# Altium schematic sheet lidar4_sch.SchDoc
size A4; PageSetup: Record=PageOptions¦CenterHorizontal=True¦CenterVertical=True¦PrintScale=1.00¦XCorrection=1.00¦YCorrection=1.00¦PrintKind=0¦BorderSize=5000000¦LeftOffset=0¦BottomOffset=0¦Orientation=2¦PaperLength=1000¦PaperWidth=1000¦Scale=100¦PaperSource=7¦PrintQuality=-3¦MediaType=1¦DitherType=10¦PrintScaleMode=1¦PaperKind=A4¦PaperIndex=9
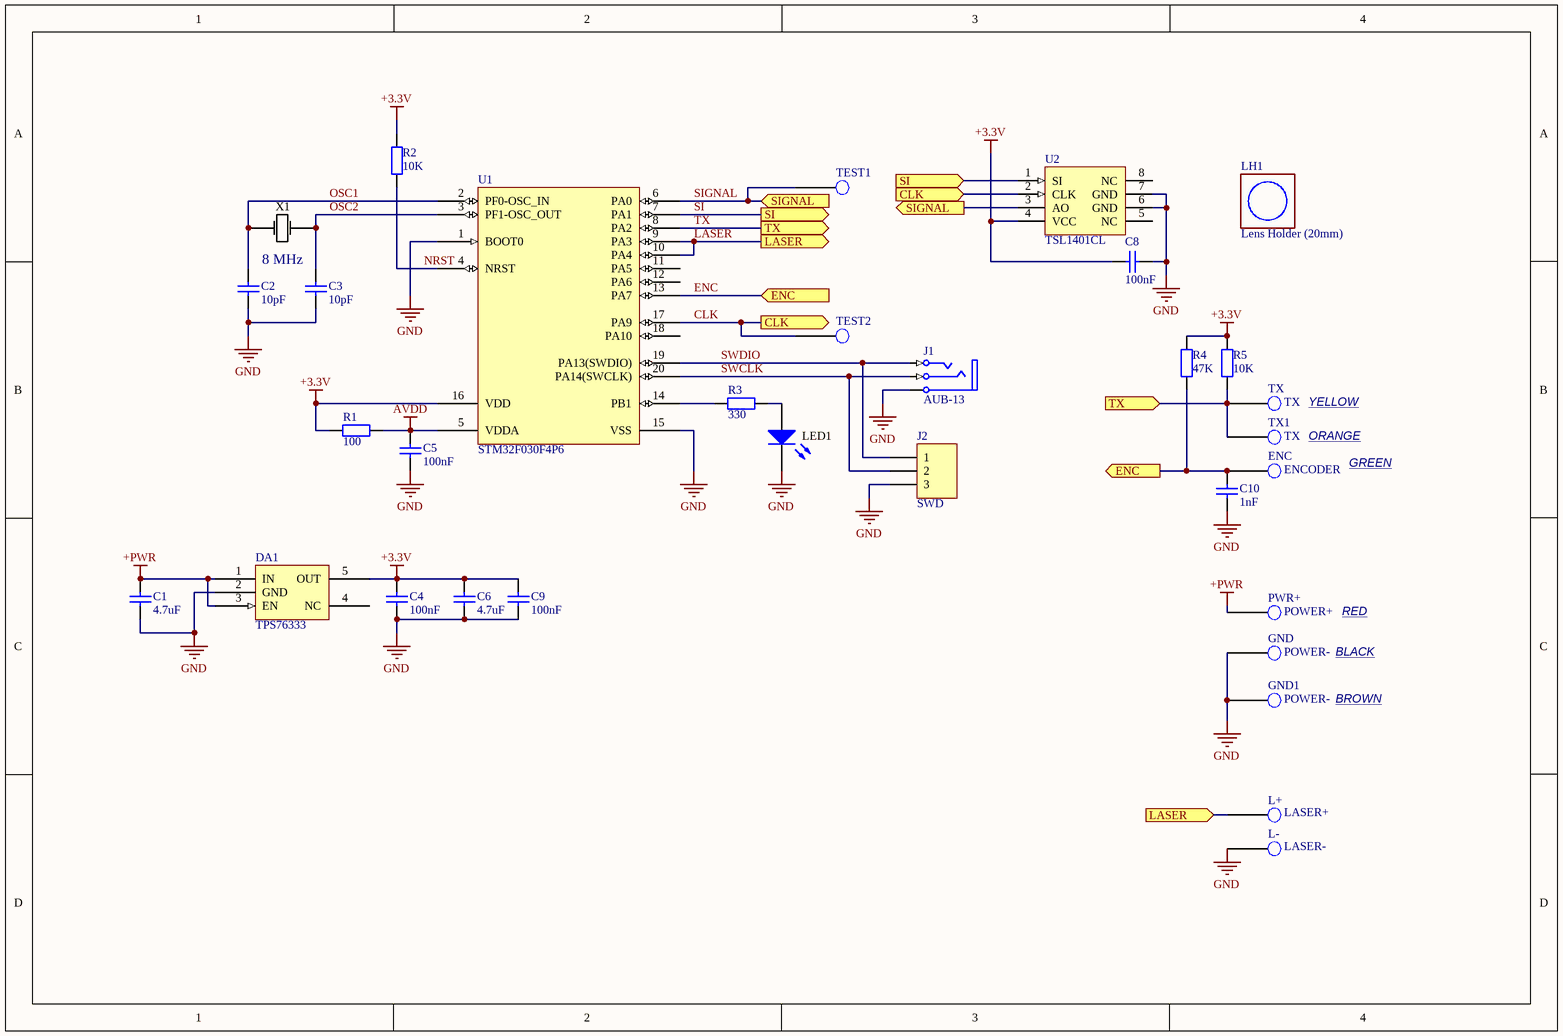
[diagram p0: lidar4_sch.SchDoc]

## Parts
C1  4.7uF  [CAPC2012X135N]
C2  10pF  [CAPC1608X90N]
C3  10pF  [CAPC1608X90N]
C4  100nF  [CAPC1608X90N]
C5  100nF  [CAPC1608X90N]
C6  4.7uF  [CAPC2012X135N]
C8  100nF  [CAPC1608X90N]
C9  100nF  [CAPC1608X90N]
C10  1nF  [CAPC1608X90N]
DA1  TPS76333  [SOT23-5]
ENC  ENCODER  [Ext_hole]
GND  POWER-  [Ext_hole]
GND1  POWER-  [Ext_hole]
J1  AUB-13  [AUB-13]
J2  SWD  [HDR1X3]
L+  LASER+  [Ext_hole]
L-  LASER-  [Ext_hole]
LED1  LED  [LED_0603]  (value not drawn)
LH1  Lens Holder (20mm)  [LENS_HOLDER_20MM_ADJ]
PWR+  POWER+  [Ext_hole]
R1  100  [RESC1608X55N]
R2  10K  [RESC1608X55N]
R3  330  [RESC1608X55N]
R4  47K  [RESC1608X55N]
R5  10K  [RESC1608X55N]
TEST1  Pad  [Ext_pad]  (value not drawn)
TEST2  Pad  [Ext_pad]  (value not drawn)
TX  TX  [Ext_hole]
TX1  TX  [Ext_hole]
U1  STM32F030F4P6  [TSSOP65P640X120-20N]
U2  TSL1401CL  [TSL1401CL_2]
X1  value 8 MHz  [SX-6 QUARTZ]  (hidden comment: Quartz)

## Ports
CLK (in), CLK (out), ENC (in), ENC (out), LASER (in), LASER (out), SI (in), SI (out), SIGNAL (in), SIGNAL (out), TX (in), TX (out)

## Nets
+3.3V: C4.2 C6.2 C8.2 C9.2 DA1.5(OUT) R1.1 R2.1 R4.1 R5.1 U1.16(VDD) U2.4(VCC)
+PWR: C1.2 DA1.1(IN) DA1.3(EN) PWR+.1(Pad)
AVDD: C5.2 R1.2 U1.5(VDDA)
GND: C1.1 C2.1 C3.1 C4.1 C5.1 C6.1 C8.1 C9.1 C10.1 DA1.2(GND) GND.1(Pad) GND1.1(Pad) J1.5(S) J2.3 L-.1(Pad) LED1.2(K) U1.1(BOOT0) U1.15(VSS) U2.6(GND) U2.7(GND)
CLK: TEST2.1(Pad) U1.17(PA9) U2.2(CLK) ; port CLK
ENC: C10.2 ENC.1(Pad) R4.2 U1.13(PA7) ; port ENC
LASER: L+.1(Pad) U1.9(PA3) U1.10(PA4) ; port LASER
NRST: R2.2 U1.4(NRST)
OSC1: C2.2 U1.2(PF0-OSC_IN) X1.1
OSC2: C3.2 U1.3(PF1-OSC_OUT) X1.3
SI: U1.7(PA1) U2.1(SI) ; port SI
SIGNAL: TEST1.1(Pad) U1.6(PA0) U2.3(AO) ; port SIGNAL
SWCLK: J1.3(R) J2.2 U1.20(PA14(SWCLK))
SWDIO: J1.1(T) J2.1 U1.19(PA13(SWDIO))
TX: R5.2 TX.1(Pad) TX1.1(Pad) U1.8(PA2) ; port TX
NetLED1_1: LED1.1(A) R3.1
NetR3_2: R3.2 U1.14(PB1)

Not connected (* = marked no-connect by the designer): DA1 4(NC); U1 11(PA5) 12(PA6) 18(PA10); U2 5(NC) 8(NC)

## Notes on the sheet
- YELLOW
- ORANGE
- GREEN
- BLACK
- RED
- BROWN

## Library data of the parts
C1-C6 C8-C10 = CC0805: Chip capacitor; Voltage: 25V
DA1 = TPS76333: LDO
ENC GND GND1 L+ L- PWR+ TEST1 TEST2 TX TX1 = Ext Pad: Pad for wire
J1 = Phonejack3: Jack Socket, 1/4" [6.5mm], Thru-Hole, Vertical, 3-Conductor Open Circuit (Non-Normalling); PackageDocument: 2003; PCB_Layout: Complies with manufacturer's recommendation.; DrillAndSlotSize: Corresponds to nominal value.
J2 = Header 3: Header, 3-Pin
LED1 = LED_0603
LH1 = M12 Lens Holder
R1-R5 = RC0805: Chip resistor; Tolerance: 5%
U1 = STM32F030F4P6: Value-line ARM-based 32-bit MCU with 16 to 64-KB Flash, timers,  ADC, communication interfaces, 2.4-3.6 V operation
U2 = TSL1401CL: Light sensor
X1 = Quartz_SX-6: Quartz_SX-6 (SMD06035C4)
